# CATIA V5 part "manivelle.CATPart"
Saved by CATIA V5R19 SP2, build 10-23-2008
Part number: manivelle
Publications: "diam_cyl"
Bounding box of the stored display mesh (mm): x -7.954 to 42.5, y -30 to 45.75, z -7.954 to 7.954
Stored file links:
  F:\Projet CAO\pièces et assemblages\mécanisme 577\577-SaintAime\577-SaintAime\manivelle.CATPart
  F:\Projet CAO\pièces et assemblages\mécanisme 577\577-SaintAime\577-SaintAime\mecanisme577_parametre.CATProduct
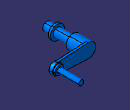
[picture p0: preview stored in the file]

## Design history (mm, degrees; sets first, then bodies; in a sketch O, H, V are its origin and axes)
Parameters
  `bras de levier` = 36.5 mm
  diam_doigt = 6 mm
External parameters (linked from other documents)
  External.largeur_pivot = 18 mm
  External.diam_pivot = 5 mm
Set1
  Plane1: type Offset, RefPlane yz-plane, Offset 36.5 {= `bras de levier`}
  Plane2: type Offset, RefPlane face of Shaft1, Offset 1.25
Body1 (main body)
  Sketch1 on yz-plane, origin (0, 0, 0), H (0, 1, 0), V (0, 0, 1)
    point P1 (-30, 0)
    line L1 (-30, 0) -> (-30, 5)
    line L2 (-30, 5) -> (-20.5, 5)
    line L3 (-20.5, 5) -> (-20.5, 8)
    line L4 (-20.5, 8) -> (-18, 8)
    line L5 (-18, 8) -> (-18, 5)
    point P6 (-18, 5)
    line L6 (-18, 5) -> (0, 5)
    point P7 (0, 5)
    line L7 (0, 5) -> (0, 8)
    point P8 (0, 8)
    line L8 (0, 8) -> (18, 8)
    line L9 (18, 8) -> (18, 0)
    point P10 (18, 0)
    line L10 (18, 0) -> (-30, 0)
    distance L5 L7 = 18 {= External.largeur_pivot}
    distance L3 L5 = 2.5
    distance L7 L9 = 18
    distance L6 L10 = 5 {= External.diam_pivot}
    distance L8 H = 8 {= External.diam_pivot  + 3 mm}
    distance L1 L3 = 9.5
    coincidence: P1 H, P6 L2, P7 V, P8 L4, P10 H
    vertical: L1 V, L3 V, L5 V, L7 V, L9 V
    horizontal: L2 H, L4 H, L6 H, L8 H, L10 H
  Shaft1: profile Sketch1, axis Sketch1.L10, angle 360
  Loft1: solid, Sections (Sketch6; Sketch5)
  Sketch2 on Plane2, origin (0, 16.75, 0), H (1, 0, 0), V (0, 0, 1)
    circle A1 centre (36.5, 0) radius 6
    point P1 (36.5, 0)
    reference projected line E1 (36.5, 6) -> (36.5, -6) from edge [face of Loft1 | face of Loft1]
    radius A1 = 6 {= (diam_doigt /2) + 3 mm}
    coincidence: P1 H, P1 E1
  Pad1: profile Sketch2, direction (0, -1, 0), length 2, mirrored extent
  Sketch3 on start face of Pad1, origin (0, 18.75, 0), H (-1, 0, 0), V (0, 0, 1)
    circle A1 centre (-36.5, 0) radius 5
    point P1 (-36.5, 0)
    reference projected circle E1 centre (-36.5, 0) radius 6 from edge [start face of Pad1 | face of Pad1 from Sketch2.A1]
    radius A1 = 5 {= (diam_doigt /2) + 2 mm}
    coincidence: P1 H
    concentricity: A1 E1
  Pad2: profile Sketch3, direction (0, 1, 0), length 2
  Sketch4 on end face of Pad2, origin (0, 20.75, 0), H (-1, 0, 0), V (0, 0, 1)
    circle A1 centre (-36.5, 0) radius 3
    point P1 (-36.5, 0)
    reference projected circle E1 centre (-36.5, 0) radius 6 from edge [start face of Pad1 | face of Pad1 from Sketch2.A1]
    radius A1 = 3 {= diam_doigt /2}
    coincidence: P1 H
    concentricity: A1 E1
  Pad3: profile Sketch4, direction (0, 1, 0), length 25
  Sketch5 on Plane1, origin (36.5, 0, 0), H (0, 1, 0), V (0, 0, 1)
    line L1 (15.5, 6) -> (15.5, -6)
    line L2 (15.5, -6) -> (18, -6)
    line L3 (18, -6) -> (18, 6)
    line L4 (18, 6) -> (15.5, 6)
    reference projected line E1 (15.5, 8) -> (15.5, -8) from Sketch6.L2
    distance L3 L1 = 2.5
    distance L4 L2 = 12
    vertical: L1 V, L3 V
    horizontal: L2 H, L4 H
    symmetry: L4 L2 H
    coincidence: L1 E1
  Sketch6 on yz-plane, origin (0, 0, 0), H (0, 1, 0), V (0, 0, 1)
    projected line E1 (18, 8) -> (18, -8) from edge [face of Shaft1 from Sketch1.L8 | face of Shaft1 from Sketch1.L9]
    line L1 (18, 8) -> (15.5, 8)
    line L2 (15.5, 8) -> (15.5, -8)
    line L3 (15.5, -8) -> (18, -8)
    distance E1 L2 = 2.5
    horizontal: L1 H, L3 H
    vertical: L2 V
